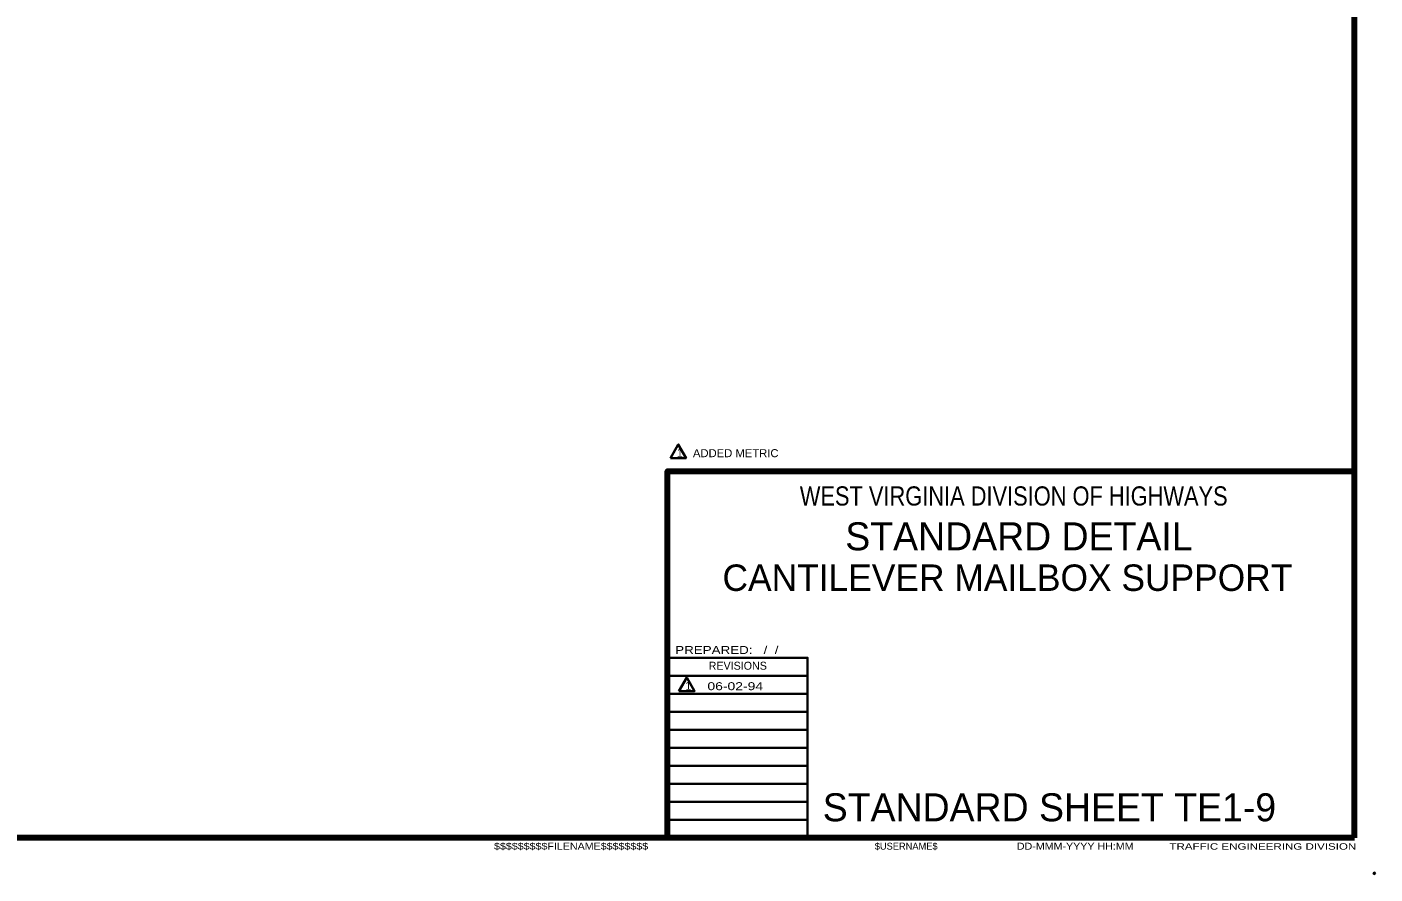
# Model space of a CAD drawing. Extents: x -123 to 733, y -435 to 109.
# Drawn here: x 304.9 to 732.6, y -435.4 to -166.6 of the extents above; entities that cross this region are included whole.
import ezdxf
from ezdxf.enums import TextEntityAlignment as Align

# ---------------------------------------------------------------- set-up
doc = ezdxf.new("R2010")
doc.units = 0
doc.header["$LTSCALE"] = 0.96
doc.header["$PDMODE"] = 32
doc.header["$PDSIZE"] = 0.48
doc.layers.add('1', color=7, linetype='Continuous', lineweight=35)
doc.layers.add('61', color=7, linetype='Continuous', lineweight=35)

msp = doc.modelspace()

# ---------------------------------------------------------------- linework, layer by layer
at = {"layer": '1', "lineweight": 158}
for q in [(726.0936, 102.1937), (726.0936, -307.6063), (-65.5064, -423.9063)]:
    msp.add_line((726.0936, -423.9063), q, dxfattribs=at)
at = {"layer": '1', "lineweight": 13}
msp.add_line((726.0936, -423.9063), (726.0936, 102.1937), dxfattribs=at)
at = {"layer": '1'}
for p, q in [((552.5936, -372.5063), (508.0936, -372.5063)), ((552.5936, -378.2063), (508.0936, -378.2063)), ((552.5936, -384.0063), (508.0936, -384.0063)), ((552.5936, -389.7063), (508.0936, -389.7063)), ((552.5936, -395.4063), (508.0936, -395.4063)), ((552.5936, -401.1063), (508.0936, -401.1063)), ((552.5936, -406.8063), (508.0936, -406.8063)), ((552.5936, -412.5063), (508.0936, -412.5063)), ((552.5936, -418.2063), (508.0936, -418.2063))]:
    msp.add_line(p, q, dxfattribs=at)
for points in [[(509.0443, -303.4502), (511.5443, -299.1201), (514.0443, -303.4502)], [(511.7492, -377.4025), (514.2492, -373.0724), (516.7492, -377.4025)]]:
    msp.add_lwpolyline(points, close=True, dxfattribs=at)
at = {"layer": '1', "lineweight": 158}
msp.add_lwpolyline([(508.0936, -423.9063), (508.0936, -307.6063), (726.0936, -307.6063)], dxfattribs=at)
at = {"layer": '1'}
msp.add_lwpolyline([(552.5936, -423.9063), (552.5936, -366.8063), (508.0936, -366.8063)], dxfattribs=at)
msp.add_point((732.3936, -435.2063), dxfattribs=at)
at = {"layer": '61', "lineweight": 53}
for q in [(573.3936, -423.9063), (573.3936, -423.9063), (573.3936, -423.9063), (573.6936, -423.9063), (573.6936, -423.9063)]:
    msp.add_line((726.0936, -423.9063), q, dxfattribs=at)

# ---------------------------------------------------------------- texts
at = {"layer": '1'}
for s, height, p in [('1', 2.54, (512.0468, -303.0126)), ('STANDARD DETAIL', 8.881, (619.6436, -332.7063)), ('CANTILEVER MAILBOX SUPPORT', 8.391, (615.9918, -345.5983)), ('1', 2.54, (514.7517, -376.9649))]:
    msp.add_text(s, height=height, dxfattribs=at).set_placement(p, align=Align.CENTER)
for s, height, width, p in [('ADDED METRIC', 2.54, 1.05, (529.7831, -303.154)), ('WEST VIRGINIA DIVISION OF HIGHWAYS', 6.089, 0.85, (617.9936, -318.5063)), ('06-02-94', 2.54, 1.3, (529.6329, -377.1063))]:
    msp.add_text(s, height=height, dxfattribs=dict(at, width=width)).set_placement(p, align=Align.CENTER)
for s, height, width, p in [('PREPARED:   /  /  ', 2.537, 1.25, (510.5936, -365.6063)), ('$$$$$$$$$FILENAME$$$$$$$$', 2.2, 1.15, (453.0936, -427.7063)), ('DD-MMM-YYYY HH:MM', 2.2, 1.15, (618.9936, -427.7063)), ('TRAFFIC ENGINEERING DIVISION', 2.031, 1.35, (667.3936, -427.7063))]:
    msp.add_text(s, height=height, dxfattribs=dict(at, width=width)).set_placement(p)
for s, height, p in [('REVISIONS', 2.537, (521.1936, -370.6063)), ('STANDARD SHEET TE1-9 ', 8.881, (557.3936, -418.7063)), ('$USERNAME$', 2.2, (573.8936, -427.7063))]:
    msp.add_text(s, height=height, dxfattribs=at).set_placement(p)

doc.saveas('drawing.dxf')
